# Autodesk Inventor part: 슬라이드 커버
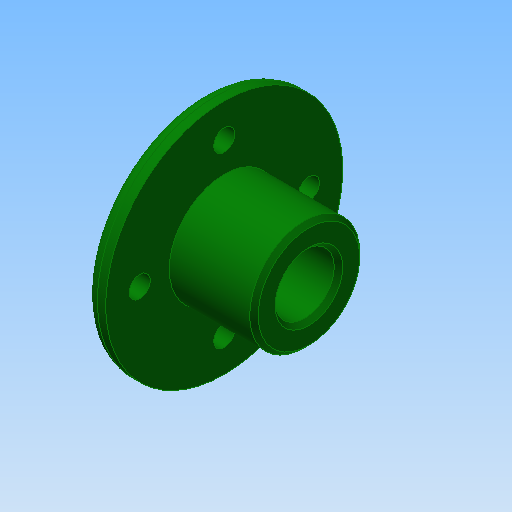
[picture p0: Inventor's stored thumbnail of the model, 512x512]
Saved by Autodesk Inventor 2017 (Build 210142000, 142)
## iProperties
Created: 2015-12
Part Number: 슬라이드 커버
Document SubType Name: Modeling
Designer: mdu
Density: 2.71 g/cm^3
Material: 알루미늄 6061
Mass: 49.5251 g
Surface Area: 80.5945 cm^2
Volume: 18.2749 cm^3
Appearance: 진녹색
Author: mdu
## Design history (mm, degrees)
sketch "스케치1"
  geometry: L1 (-12.5, 0)-(12.5, 0); L2 (-12.5, 0)-(-12.5, 28); L3 (-12.5, 28)-(-7.5, 28); L4 (-7.5, 28)-(-7.5, 13); L5 (-7.5, 13)-(12.5, 13); L6 (12.5, 13)-(12.5, 0); 2 further points
  constraints: 12 end point, 3 perpendicular, 1 coincident, 1 horizontal, 1 midpoint, 1 parallel
  dimensions: "d1" = 56 diameter of L3 L1; "d2" = 26 diameter of L5 L1; "d5" = 5 distance of L2.end L3.end; "d32" = 20 distance of L4.end L5.end
revolve "회전1" sketch "스케치1" stored, may be unused: angle "d6" = 90 deg
sketch "스케치2" dims "d33" = 40
  geometry: 3 further points
  constraints: 2 vertical alignment, 1 coincident, 2 other
hole "구멍1" sketch "스케치2" at (0, 20) diameter "d8" = 5; stored, may be unused: countersink angle "d12" = 90 deg, drill point angle "d14" = 118 deg; dims "d9" = 6, "d10" = 8, "d11" = 4.4, "d13" = 8
hole "구멍2" diameter "d20" = 14; stored, may be unused: countersink angle "d24" = 90 deg, drill point angle "d26" = 0 deg; dims "d18" = 10, "d19" = 10, "d21" = 6, "d22" = 8, "d23" = 4.4, "d25" = 8
fillet "모깎기1" dims "d27" = 3
chamfer "모따기1" distance "d29" = 1; stored, may be unused: second distance "d30" = 2, angle "d31" = 45 deg
node "솔리드1"
pattern_circular "원형 패턴1" dims angle "d16" = 360 deg
